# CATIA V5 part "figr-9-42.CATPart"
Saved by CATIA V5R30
Part number: Part1
Bounding box of the stored display mesh (mm): x -60 to 60, y -70.383 to 65.913, z 0 to 125
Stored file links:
  D:\PROJECTS\CATIA V56R 2020\Resources\Parts File\c09_catia_v5_6r2020_prt\figr-9-42.CATPart
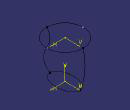
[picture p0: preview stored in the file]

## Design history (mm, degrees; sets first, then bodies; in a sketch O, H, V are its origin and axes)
Set1
  Plane1: type Offset, RefPlane xy-plane, Offset 125
Body1 (main body)
  Sketch1 on xy-plane, origin (0, 0, 0), H (1, 0, 0), V (0, 1, 0)
    ellipse A1 centre (0, 0) semi-axes 50, 30 rotation 270
    point P1 (30, 0)
    coincidence: P1 H, A1 P1
  Sketch2 on Plane1, origin (0, 0, 125), H (1, 0, 0), V (0, 1, 0)
    circle A1 centre (0, 0) radius 60
  Sketch3 on yz-plane, origin (0, 0, 0), H (0, 1, 0), V (0, 0, 1)
    arc A1 centre (-129.6632, 77.2731) radius 195.5761 from (50, 0) to (60, 125) ccw
    point P2 (50, 0)
    point P3 (60, 125)
    reference projected line E1 (-50, 0) -> (50, 0) from edge of Sketch1
    reference projected line E2 (-60, 125) -> (60, 125) from edge of Sketch2
    coincidence: P2 H, P2 E1, P3 E2
  Sketch4 on yz-plane, origin (0, 0, 0), H (0, 1, 0), V (0, 0, 1)
    spline S1 through (-50, 0) (-70, 40) (-50, 100) (-60, 125)
    reference projected line E1 (-60, 125) -> (60, 125) from edge of Sketch2
    reference projected line E2 (-50, 0) -> (50, 0) from edge of Sketch1
    point P1 (-60, 125)
    point P2 (-50, 0)
    coincidence: P1 E1, P2 E2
